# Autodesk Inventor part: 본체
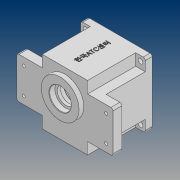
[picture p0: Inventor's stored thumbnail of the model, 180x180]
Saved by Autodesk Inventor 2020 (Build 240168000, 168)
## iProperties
Created: 2020-07
Part Number: 본체
Material: 일반
Document SubType Name: Modeling
Designer: PC312-
Density: 1 g/cm^3
Appearance: 기본값
Author: PC312-
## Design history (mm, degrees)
sketch "스케치1"
  geometry: L1 (-47, 47)-(47, 47); L2 (47, 47)-(47, -47); L3 (47, -47)-(-47, -47); L4 (-47, -47)-(-47, 47); L5 (-47, 47)-(47, -47); L6 (47, 47)-(-47, -47); 1 further point
  constraints: 12 end point, 2 midpoint, 2 parallel, 1 horizontal, 1 perpendicular
  dimensions: "d0" = 94 distance of L1.start L1.end; "d1" = 94 distance of L3.end L1.start
extrude "돌출1" new body sketch "스케치1" stored distance "d2" = 80; taper "d3" = 0 deg
sketch "스케치2"
  geometry: L1 (-47, -47)-(-47, 47) reference; L2 (-47, 30)-(-70, 30); L3 (-70, 30)-(-70, -30); L4 (-70, -30)-(-47, -30); L5 (-47, 30)-(-47, -30); L6 (47, 47)-(47, -47) reference; L7 (47, 30)-(47, -30); L8 (47, -30)-(70, -30); L9 (70, -30)-(70, 30); L10 (70, 30)-(47, 30); 1 further point
  constraints: 16 end point, 4 horizontal, 4 point on line, 3 vertical
  dimensions: "d5" = 70 distance from line of L9 point (0, 0); "d6" = 70 distance from line of point (0, 0) L3; "d7" = 60 distance of L2.end L3.end; "d8" = 60 distance of L8.end L9.end; "d9" = 30 distance from line of point (0, 0) L2; "d10" = 30 distance from line of point (0, 0) L10
extrude "돌출2" join sketch "스케치2" distance "d11" = 13; taper "d12" = 0 deg
sketch "스케치3"
  geometry: L1 (47, 47)-(47, -47) reference; L2 (47, 47)-(33, 47); L3 (33, 47)-(33, 30); L4 (33, 30)-(47, 30); L5 (47, 30)-(47, 47); L6 (47, 30)-(70, 30) reference; L7 (47, -47)-(-47, -47) reference; L8 (47, -47)-(33, -47); L9 (33, -47)-(33, -30); L10 (33, -30)-(47, -30); L11 (47, -30)-(47, -47); L12 (70, -30)-(47, -30) reference; 6 further points
  constraints: 16 end point, 4 parallel, 2 horizontal, 2 horizontal alignment, 2 midpoint, 2 perpendicular
  dimensions: "d13" = 33 distance from line of L3 point (0, 0); "d14" = 33 distance from line of L9 point (0, 0)
extrude "돌출3" cut sketch "스케치3" distance "d15" = 70; taper "d16" = 0 deg
sketch "스케치4"
  geometry: C1 r 43 at (0, 0); 1 further point
  constraints: 1 centre point, 1 coincident
  dimensions: "d17" = 86 diameter of C1
extrude "돌출4" cut sketch "스케치4" distance "d18" = 9; taper "d19" = 0 deg
sketch "스케치5"
  geometry: C1 r 40 at (0, 0); 1 further point
  constraints: 1 centre point, 1 coincident
  dimensions: "d20" = 80 diameter of C1
extrude "돌출5" cut sketch "스케치5" distance "d21" = 62; taper "d22" = 0 deg
sketch "스케치6"
  geometry: C1 r 17.5 at (0, 11); C2 r 11 at (0, -20); A1 r 21 centre (0, 11) between (8.978, -7.984) and (-8.978, -7.984); A2 r 15 centre (0, -20) between (-8.978, -7.984) and (8.978, -7.984); 1 further point
  constraints: 4 centre point, 4 point on circle, 2 coincident, 2 vertical alignment
  dimensions: "d23" = 42 diameter of A1; "d24" = 11 distance of point (0, 0) A1.centre; "d25" = 30 diameter of A2; "d26" = 20 distance of A2.centre point (0, 0); "d27" = 35 diameter of C1; "d28" = 22 diameter of C2
extrude "돌출6" join sketch "스케치6" distance "d29" = 7; taper "d30" = 0 deg
sketch "스케치8"
  geometry: C1 r 27.5 at (0, 11); 1 further point
  constraints: 1 centre point, 1 vertical alignment
  dimensions: "d31" = 55 diameter of C1; "d32" = 11 distance of point (0, 0) C1.centre
extrude "돌출7" join sketch "스케치8" distance "d33" = 7; taper "d34" = 0 deg
sketch "스케치9"
  geometry: L1 (38.5, 47)-(-16.5, 47) reference; L2 (11, 47)-(11, 6.865); L3 (11, 47)-(27, 47); L4 (27, 38.7)-(23.5, 38.7); L5 (27, 47)-(27, 38.7); L6 (23.5, 38.7)-(23.5, 34); L7 (23.5, 34)-(28.5, 34); L8 (28.5, 34)-(28.5, 24); L9 (28.5, 24)-(11, 24); 1 further point
  constraints: 16 end point, 4 vertical, 3 horizontal, 2 point on line, 1 midpoint
  dimensions: "d35" = 11 distance from line of point (0, 0) L2; "d37" = 32 diameter of L5 L2; "d38" = 25 diameter of L6 L2; "d39" = 35 diameter of L8 L2; "d41" = 23 distance between parallel lines of L1 L9; "d42" = 10 distance between parallel lines of L9 L7; "d43" = 8.3 distance between parallel lines of L4 L1
revolve "회전1" sketch "스케치9" stored, may be unused: angle "d44" = 90 deg
sketch "스케치10"
  geometry: C1 r 11 at (0, 0) reference; C2 r 9.5 at (0, 0); 1 further point
  constraints: 1 centre point, 1 coincident
  dimensions: "d45" = 19 diameter of C2
extrude "돌출8" cut sketch "스케치10" distance "d46" = 3; taper "d47" = 0 deg
sketch "스케치11"
  geometry: A1 r 36 centre (0, 0) between (-36, 0) and (36, 0); A2 r 4 centre (-36, 0) between (-37.576, -3.677) and (-37.576, 3.677); A3 r 4 centre (36, 0) between (37.576, 3.677) and (37.576, -3.677); A4 r 1.5 centre (-38.167, 5.055) between (-39.654, 5.252) and (-37.576, 3.677); A5 r 1.5 centre (-38.167, -5.055) between (-37.576, -3.677) and (-39.654, -5.252); A6 r 40 centre (0, 0) between (-39.654, 5.252) and (-39.654, -5.252) reference; A7 r 1.5 centre (38.167, 5.055) between (37.576, 3.677) and (39.654, 5.252); A8 r 1.5 centre (38.167, -5.055) between (39.654, -5.252) and (37.576, -3.677); 1 further point
  constraints: 18 point on circle, 8 tangent, 7 centre point, 2 horizontal alignment, 1 coincident
  dimensions: "d48" = 72 diameter of A1; "d49" = 8 diameter of A2; "d50" = 8 diameter of A3; "d51" = 3 diameter of A4; "d52" = 3 diameter of A5; "d53" = 3 diameter of A7; "d54" = 3 diameter of A8
extrude "돌출9" join sketch "스케치11" distance "d55" = 62; taper "d56" = 0 deg
sketch "스케치12"
  geometry: L1 (-70, -30)-(-70, 30) reference; 3 further points
  dimensions: "d57" = 19 vertical distance of point (0, 0) point (-60, 19); "d58" = 19 vertical distance of point (0, 0) point (-60, -19); "d59" = 10 distance from line of L1 point (-60, -19); "d60" = 10 distance from line of L1 point (-60, 19)
hole "구멍1" sketch "스케치12" at (-60, 19), (-60, -19) diameter "d61" = 4.5; stored, may be unused: countersink angle "d65" = 90 deg, drill point angle "d67" = 118 deg; dims "d62" = 20, "d63" = 10, "d64" = 5, "d66" = 8
fillet "모깎기1" dims "d68" = 3
sketch "스케치13"
  geometry: 3 further points
  dimensions: "d69" = 40 horizontal distance of point (40, 40) point (0, 0); "d70" = 40 horizontal distance of point (40, -40) point (0, 0); "d71" = 40 horizontal distance of point (40, 40) point (0, 0); "d72" = 40 horizontal distance of point (40, -40) point (0, 0)
hole "구멍2" sketch "스케치13" at (40, 40), (40, -40) diameter "d73" = 7; stored, may be unused: countersink angle "d77" = 90 deg, drill point angle "d79" = 118 deg; dims "d74" = 20, "d75" = 10, "d76" = 5, "d78" = 8
sketch "스케치14"
  geometry: A1 r 4 centre (-36, 0) between (-37.576, -3.677) and (-37.576, 3.677) reference; 2 further points
  constraints: 1 coincident
hole "구멍3" sketch "스케치14" at (-36, 0) diameter "d80" = 3.242; stored, may be unused: countersink angle "d84" = 90 deg, drill point angle "d86" = 118 deg; dims "d81" = 7, "d82" = 10, "d83" = 5, "d85" = 9
sketch "스케치15"
  geometry: A1 r 4 centre (36, 0) between (37.576, 3.677) and (37.576, -3.677) reference; 2 further points
  constraints: 1 coincident
hole "구멍4" sketch "스케치15" at (36, 0) diameter "d87" = 3.242; stored, may be unused: countersink angle "d91" = 90 deg, drill point angle "d93" = 118 deg; dims "d88" = 7, "d89" = 10, "d90" = 5, "d92" = 9
fillet "모깎기2" dims "d94" = 3
chamfer "모따기1" distance "d95" = 1; stored, may be unused: second distance "d96" = 2, angle "d97" = 45 deg
chamfer "모따기2" distance "d98" = 0.8; stored, may be unused: second distance "d99" = 2, angle "d100" = 30 deg
node "작업 평면1"
sketch "스케치16"
  geometry: L1 (-77, 80)-(11, 80) reference; 2 further points
  constraints: 1 coincident, 1 other
  dimensions: "d102" = 40 distance from line of L1 point (-33, 40)
feature "엠보싱1" sketch "스케치16" dims "d0" = 94, "d1" = 94, "d103" = 0.5, "d104" = 0
node "솔리드1"
mirror "미러1"
mirror "미러2"
mirror "미러3"
feature "A9D066F2-1C7D-4E18-AEED-F7BC21143FA4" dims "d61" = 4.5, "d62" = 20, "d63" = 10, "d64" = 5, "d65" = 90 deg, "d66" = 8, "d67" = 118 deg
